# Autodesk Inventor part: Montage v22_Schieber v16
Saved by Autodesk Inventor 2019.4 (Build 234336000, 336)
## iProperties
Created: 2021-06
Part Number: Montage v22_Schieber v16
Material: Generic
Document SubType Name: Modeling
Designer: Administrator
Density: 1 g/cm^3
Appearance: Default
Title: Montage v22_Schieber v16 v2
Author: Administrator
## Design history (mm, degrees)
feature "Body1"
body "Solid1"
